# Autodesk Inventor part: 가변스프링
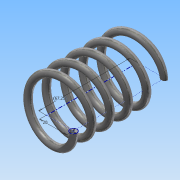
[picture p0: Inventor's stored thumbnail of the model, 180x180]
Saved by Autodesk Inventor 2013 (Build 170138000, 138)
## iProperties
Created: 2018-08
Part Number: 가변스프링
Material: 스테인리스강
Document SubType Name: Modeling
Designer: Administrator
Density: 8.08 g/cm^3
Mass: 98.0401 g
Surface Area: 98.6263 cm^2
Volume: 12.1337 cm^3
Author: Administrator
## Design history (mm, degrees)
sketch "스케치1"
  geometry: L1 (0, 0)-(20, 0); L2 (20, 0)-(20, 67.25); L3 (20, 67.25)-(0, 67.25); L4 (0, 67.25)-(0, 0); C1 r 2.5 at (20, 0)
  constraints: 8 end point, 2 parallel, 1 centre point, 1 coincident, 1 horizontal, 1 perpendicular
  dimensions: "d0" = 5 diameter of C1; "d1" = 67.25 distance of L3.end L1.start (derived); "d2" = 20 distance of L1.start L1.end
feature "코일1" pitch "d3" = 10; turns "d5" = 5; dims "d4" = 67.25 (= d1), "d6" = 0, angle "d7" = 90 deg, angle "d8" = 90 deg, "d9" = 0, "d10" = 0
sketch "스케치2"
  geometry: L1 (-22.5, 0)-(-17.5, 0) reference; 1 further point
  constraints: 1 horizontal alignment
extrude "돌출1" cut sketch "스케치2" distance "d11" = 10; taper "d12" = 0 deg
node "작업 평면1"
sketch "스케치3"
  geometry: L1 (22.5, 0)-(17.5, 0) reference; 1 further point
  constraints: 1 horizontal alignment
extrude "돌출2" cut sketch "스케치3" distance "d13" = 10; taper "d14" = 0 deg
node "솔리드1"
node "절단 모서리 투영1"
node "절단 모서리 투영2"
